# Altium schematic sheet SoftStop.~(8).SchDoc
size A
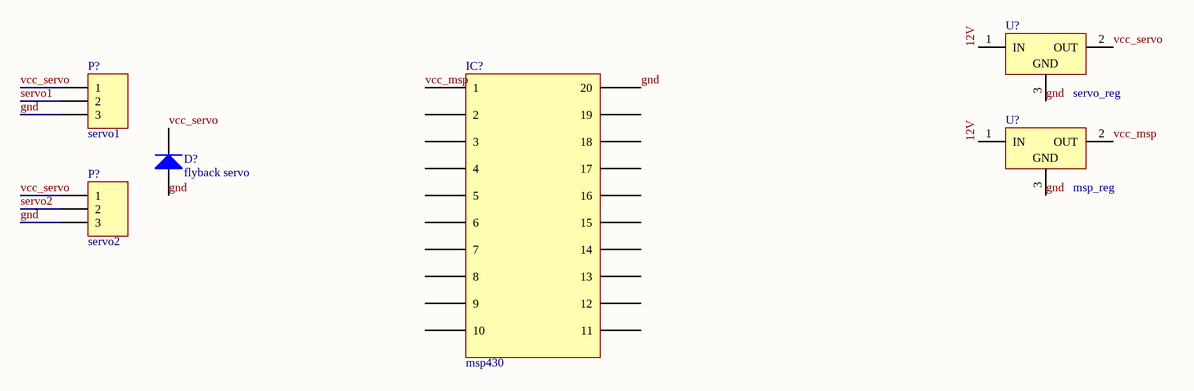
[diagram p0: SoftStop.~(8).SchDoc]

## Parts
(Parts that share a designator on the sheet are numbered #1, #2 ... from top to bottom, then left to right.)
D?  flyback servo  [DO-41]
IC?  msp430  [msp430]
P?#1  servo1  [HDR1X3H]
P?#2  servo2  [HDR1X3H]
U?#1  servo_reg  [TO220ABN]
U?#2  msp_reg  [TO220ABN]

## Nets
12V: U?#1.1(IN) U?#2.1(IN)
gnd: D?.1(A) IC?.20 P?#1.3 P?#2.3 U?#1.3(GND) U?#2.3(GND)
servo1: P?#1.2
servo2: P?#2.2
vcc_msp: IC?.1 U?#2.2(OUT)
vcc_servo: D?.2(K) P?#1.1 P?#2.1 U?#1.2(OUT)

Not connected (* = marked no-connect by the designer): IC? 2 3 4 5 6 7 8 9 10 11 12 13 14 15 16 17 18 19

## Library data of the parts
D? = Diode 1N4001: 1 Amp General Purpose Rectifier
P?#1 P?#2 = Header 3H: Header, 3-Pin, Right Angle
U?#1 U?#2 = L7805CV: Positive Voltage Regulator; Note: Tab is connected to pin 3 (GND).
